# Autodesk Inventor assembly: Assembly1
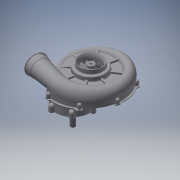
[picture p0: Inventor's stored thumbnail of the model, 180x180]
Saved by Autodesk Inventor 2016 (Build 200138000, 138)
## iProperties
Created: 2015-03
Part Number: Assembly1
Document SubType Name: Assembly
Designer: Uglješa
Author: Uglješa
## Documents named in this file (22)
- C:\Users\Ugljesa\Desktop\Turbokompr\Assembly1.iam
- C:\Users\Ugljesa\Desktop\Turbokompr\Assembly1\Design Accelerator\Spur Gears1.iam
- C:\Users\Ugljesa\Desktop\Turbokompr\Assembly1\Design Accelerator\Shaft1.iam
- C:\Users\Ugljesa\Desktop\Turbokompr\Assembly1\Design Accelerator\Shaft2.iam
- C:\Users\Ugljesa\Desktop\Turbokompr\rotor turbo kompresosra.ipt
- C:\Users\Ugljesa\Desktop\Turbokompr\Assembly1\Design Accelerator\Key Connection7.iam
- C:\Users\Ugljesa\Desktop\Turbokompr\Part12.ipt
- C:\Users\Ugljesa\Desktop\Turbokompr\Assembly1\Design Accelerator\Key Connection9.iam
- C:\Users\Ugljesa\Desktop\Turbokompr\Assembly1\Design Accelerator\V-Belt transmission2.iam
- C:\Users\Ugljesa\Desktop\Turbokompr\Assembly1\Design Accelerator\Key Connection3.iam
- C:\Users\Ugljesa\Desktop\Turbokompr\Usini dio kucista.ipt
- C:\Users\Ugljesa\Desktop\Turbokompr\Srednji dio kucista.ipt
- C:\Users\Ugljesa\Desktop\Turbokompr\Plocica za stezanje.ipt
- C:\Users\Ugljesa\Desktop\Turbokompr\Plocica za stezanje - 2.ipt
- C:\Users\Ugljesa\Desktop\Turbokompr\Plocica za stezanje - 3.ipt
- C:\Users\Ugljesa\Desktop\Turbokompr\Plocica za stezanje - 4.ipt
- C:\Users\Ugljesa\Desktop\Turbokompr\Kuciste multiplikatora.ipt
- C:\Users\Ugljesa\Desktop\Turbokompr\Assembly1\Design Accelerator\Bearing1.iam
- C:\Users\Ugljesa\Desktop\Turbokompr\Assembly1\Design Accelerator\Bearing2.iam
- C:\Users\Ugljesa\Desktop\Turbokompr\Gornji dio kucista multiplikatora.ipt
- C:\Users\Ugljesa\Desktop\Turbokompr\Assembly1\Design Accelerator\Bearing3.iam
- C:\Users\Ugljesa\Desktop\Turbokompr\Assembly1\Design Accelerator\Bearing4.iam
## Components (21 placed, 15 different names)
1. Spur Gears:1 [sub-assembly] — Mate:3, Mate:4, Flush:2, Mate:10, Mate:14, Flush:7, Flush:8, Symmetry:1
2. Shaft:1 [sub-assembly] — Mate:10, Flush:7, Flush:8, Mate:29, Flush:13, Mate:32, Flush:14
3. Shaft:2 [sub-assembly] — Flush:1, Mate:4, Flush:2, Mate:5, Mate:13, Flush:5, Mate:15, Mate:28, Flush:12, Mate:30, Mate:31
4. rotor turbo kompresosra:1 — Mate:5, Mate:13, Flush:5
5. Key Connection:1 [sub-assembly]
6. Part12:1 — Flush:1, Mate:3
7. Key Connection:2 [sub-assembly]
8. V-Belt transmission:1 [sub-assembly] — Flush:4, Angle:1, Mate:12
9. Key Connection:3 [sub-assembly] — Flush:4, Angle:1, Mate:12
10. Usini dio kucista:1 — Mate:14, Mate:15, Mate:16, Flush:6, Flush:9, Mate:17, Mate:18, Mate:19, Mate:20, Mate:21, Mate:22, Mate:23, Mate:24, Mate:25
11. Srednji dio kucista:1 — Mate:16, Flush:6, Symmetry:1, Mate:33
12. Plocica za stezanje:1 — Flush:9
13. Plocica za stezanje - 2:1 — Mate:17, Mate:18, Mate:21
14. Plocica za stezanje - 3:2 — Mate:19, Mate:20, Mate:22
15. Plocica za stezanje - 4:1 — Mate:23, Mate:24, Mate:25
16. Kuciste multiplikatora:1 — Mate:33, Mate:34, Flush:15
17. Bearing:1 [sub-assembly] — Mate:28, Flush:12
18. Bearing:2 [sub-assembly] — Mate:29, Flush:13
19. Gornji dio kucista multiplikatora:1 — Flush:15
20. Bearing:3 [sub-assembly] — Mate:30, Mate:31
21. Bearing:4 [sub-assembly] — Mate:32, Flush:14, Mate:34
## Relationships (39: Mate 25, Flush 12, Angle 1, Symmetry 1)
- Flush:1: Shaft:2 ↔ Part12:1
- Mate:3: Spur Gears:1 ↔ Part12:1
- Mate:4: Spur Gears:1 ↔ Shaft:2
- Flush:2: Spur Gears:1 ↔ Shaft:2
- Mate:5: Shaft:2 ↔ rotor turbo kompresosra:1
- Mate:10: Spur Gears:1 ↔ Shaft:1
- Flush:4: V-Belt transmission:1 ↔ Key Connection:3
- Angle:1: V-Belt transmission:1 ↔ Key Connection:3
- Mate:12: V-Belt transmission:1 ↔ Key Connection:3
- Mate:13: Shaft:2 ↔ rotor turbo kompresosra:1
- Flush:5: Shaft:2 ↔ rotor turbo kompresosra:1
- Mate:14: Spur Gears:1 ↔ Usini dio kucista:1
- Mate:15: Shaft:2 ↔ Usini dio kucista:1
- Mate:16: Usini dio kucista:1 ↔ Srednji dio kucista:1
- Flush:6: Usini dio kucista:1 ↔ Srednji dio kucista:1
- Flush:7: Spur Gears:1 ↔ Shaft:1
- Flush:8: Spur Gears:1 ↔ Shaft:1
- Flush:9: Usini dio kucista:1 ↔ Plocica za stezanje:1
- Mate:17: Usini dio kucista:1 ↔ Plocica za stezanje - 2:1
- Mate:18: Usini dio kucista:1 ↔ Plocica za stezanje - 2:1
- Mate:19: Usini dio kucista:1 ↔ Plocica za stezanje - 3:2
- Mate:20: Usini dio kucista:1 ↔ Plocica za stezanje - 3:2
- Mate:21: Usini dio kucista:1 ↔ Plocica za stezanje - 2:1
- Mate:22: Usini dio kucista:1 ↔ Plocica za stezanje - 3:2
- Mate:23: Usini dio kucista:1 ↔ Plocica za stezanje - 4:1
- Mate:24: Usini dio kucista:1 ↔ Plocica za stezanje - 4:1
- Mate:25: Usini dio kucista:1 ↔ Plocica za stezanje - 4:1
- Symmetry:1: Spur Gears:1 ↔ Srednji dio kucista:1
- Mate:28: Shaft:2 ↔ Bearing:1
- Flush:12: Shaft:2 ↔ Bearing:1
- Mate:29: Shaft:1 ↔ Bearing:2
- Flush:13: Shaft:1 ↔ Bearing:2
- Mate:30: Shaft:2 ↔ Bearing:3
- Mate:31: Shaft:2 ↔ Bearing:3
- Mate:32: Shaft:1 ↔ Bearing:4
- Flush:14: Shaft:1 ↔ Bearing:4
- Mate:33: Srednji dio kucista:1 ↔ Kuciste multiplikatora:1
- Mate:34: Kuciste multiplikatora:1 ↔ Bearing:4
- Flush:15: Kuciste multiplikatora:1 ↔ Gornji dio kucista multiplikatora:1
